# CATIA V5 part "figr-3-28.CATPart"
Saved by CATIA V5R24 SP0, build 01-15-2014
Part number: Part1
Bounding box of the stored display mesh (mm): x 0 to 71.72, y -62.404 to 71.526, z 0 to 0
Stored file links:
  D:\KAVITA\CATIA V5-6R2014 Project_ Kavita\CATIA V5-6R2014_partfiles\Partfiles\c03_catia_v5-6r2014_prt\figr-3-28.CATPart
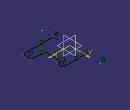
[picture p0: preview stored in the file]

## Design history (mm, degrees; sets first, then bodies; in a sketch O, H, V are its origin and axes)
Body1 (main body)
  Sketch1 on xy-plane, origin (0, 0, 0), H (1, 0, 0), V (0, 1, 0)
    axis line L1 (0, 71.5261) -> (1.8602, -62.4039)
    point P1 (0, 71.5261)
    line L2 (0.4896, 36.2738) -> (51.465, 36.2738)
    point P3 (0.4896, 36.2738)
    line L3 (51.465, 36.2738) -> (51.465, 23.0127)
    line L4 (51.465, 23.0127) -> (41.544, 23.0127)
    line L5 (41.544, 23.0127) -> (41.544, -16.3784)
    line L6 (41.544, -16.3784) -> (71.7203, -16.3784)
    line L7 (71.7203, -16.3784) -> (71.7203, -36.696)
    line L8 (71.7203, -36.696) -> (1.5031, -36.696)
    point P10 (1.5031, -36.696)
    coincidence: P1 V, P3 L1, P10 L1
    horizontal: L2 H, L4 H, L6 H, L8 H
    vertical: L3 V, L5 V, L7 V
